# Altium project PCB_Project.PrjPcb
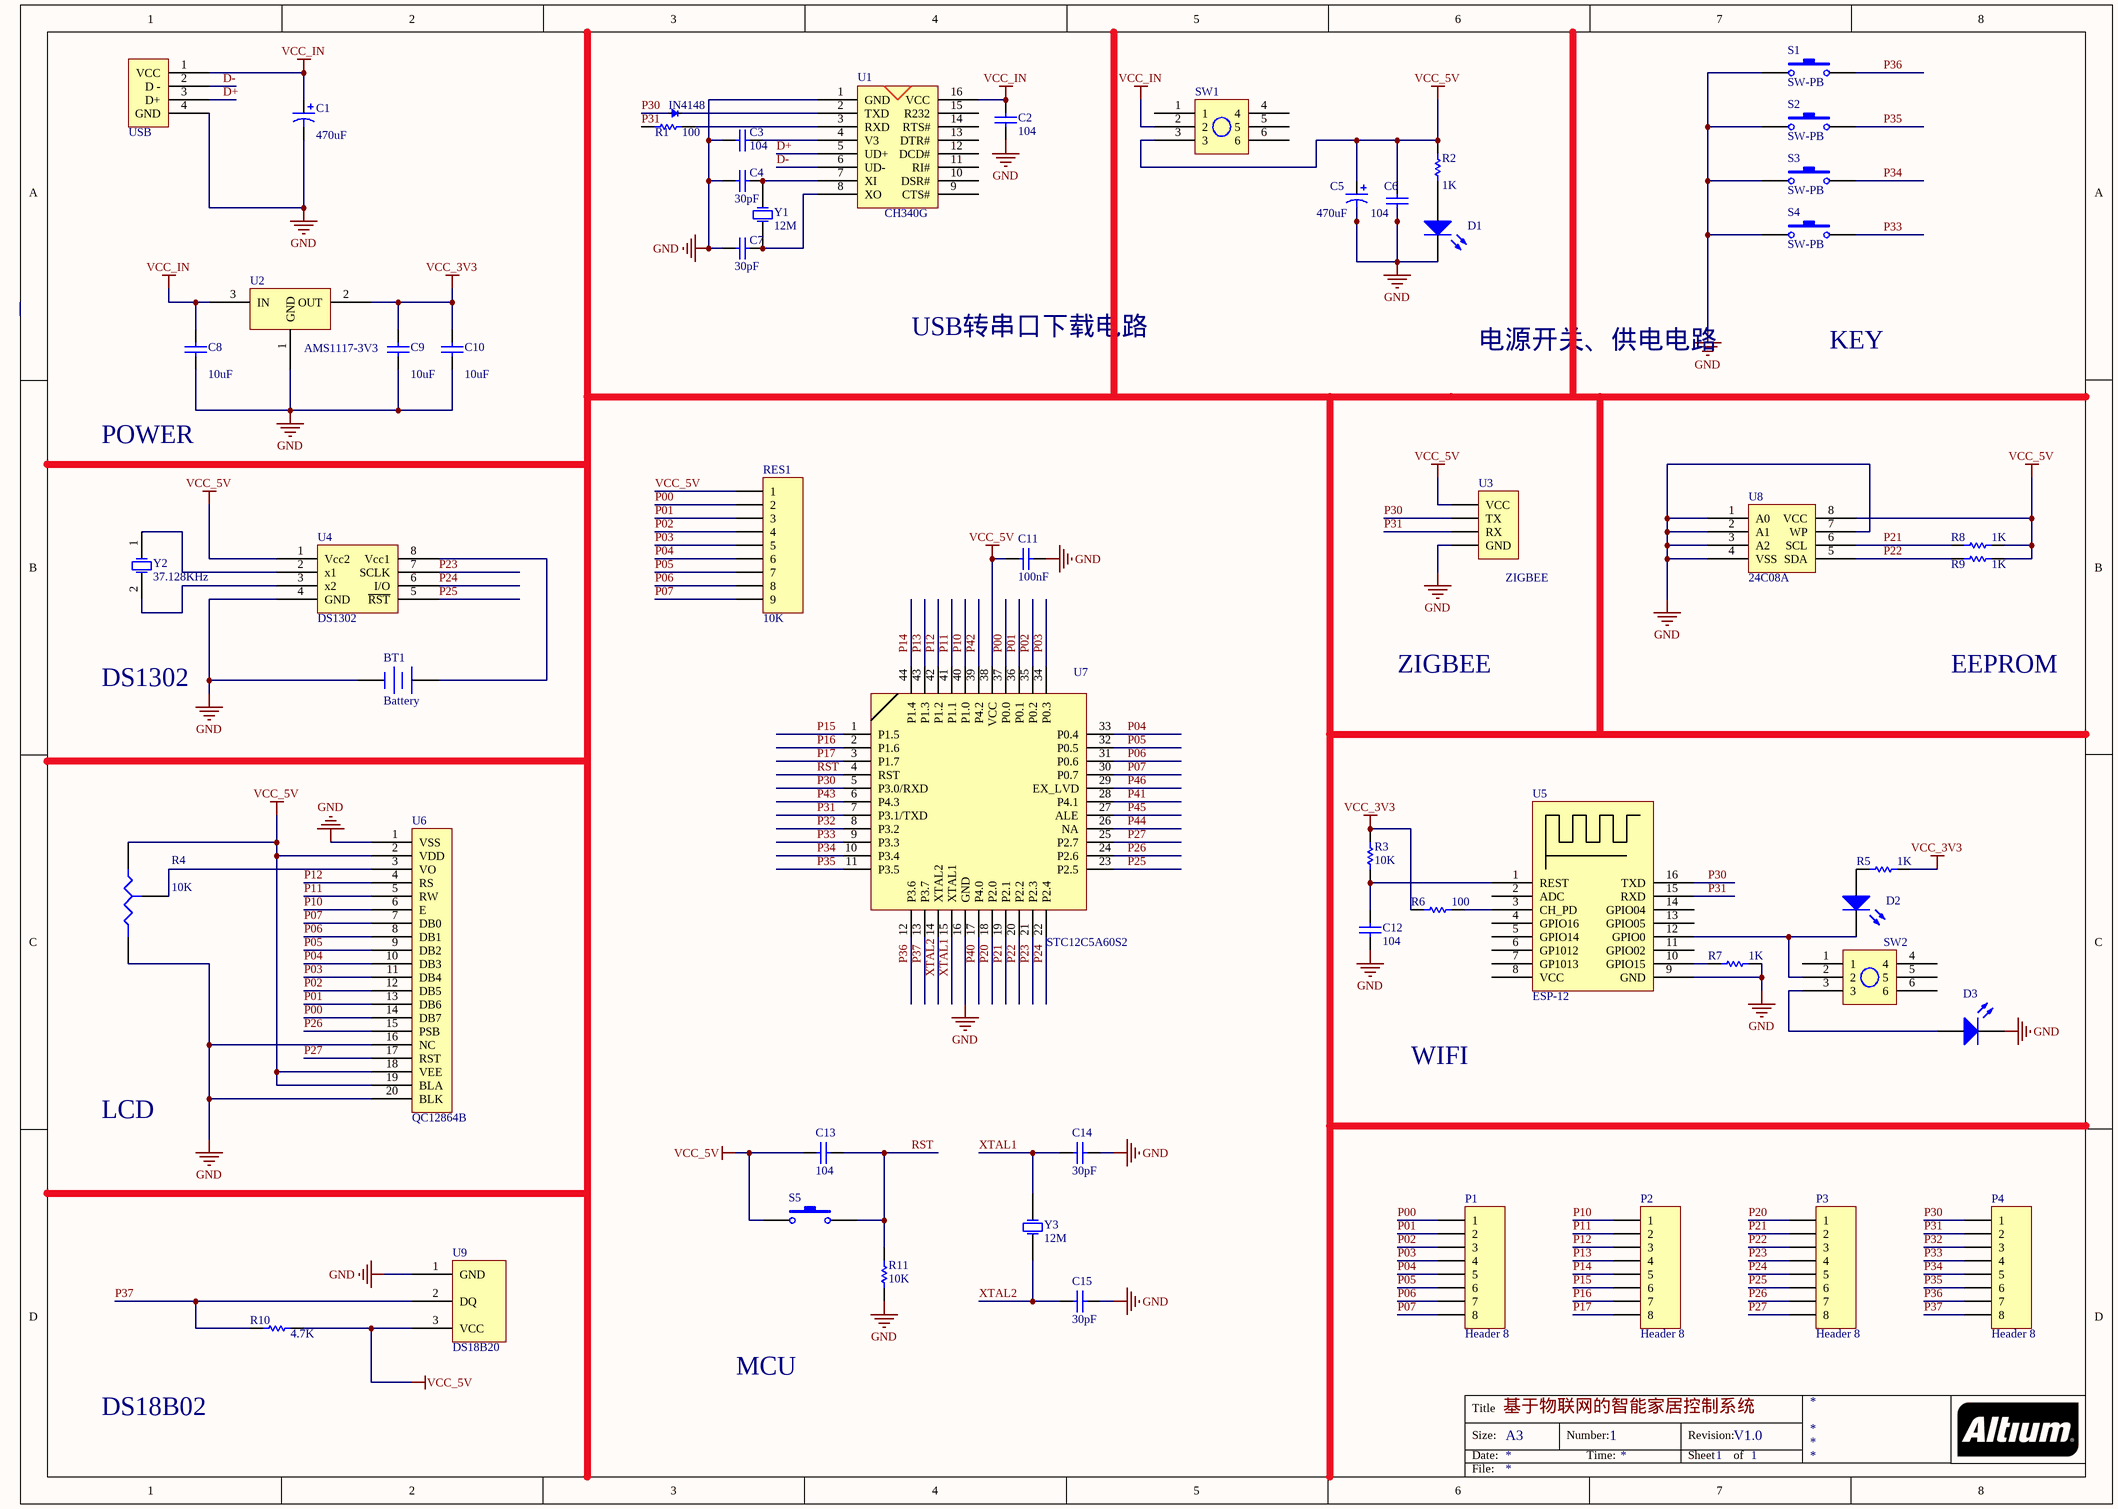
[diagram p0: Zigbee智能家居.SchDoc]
1 sheet, 56 parts. Net scope: global (net labels, ports and power ports of the same name join across sheets).
Board file: zigbee智能家居.PcbDoc

## Sheet Zigbee智能家居.SchDoc: 基于物联网的智能家居控制系统
size A3; DocumentNumber: 1; Revision: V1.0; SheetNumber: 1; SheetTotal: 1

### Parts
*1  USB  [USB-4-A-SMT]
BT1  Battery  [BATTERY]
C1  value 470uF  [8mm Cap+]  (hidden comment: Cap Pol1)
C2  value 104  [RAD-0.1]  (hidden comment: Cap)
C3  value 104  [RAD-0.1]  (hidden comment: Cap)
C4  value 30pF  [RAD-0.1]  (hidden comment: Cap)
C5  value 470uF  [8mm Cap+]  (hidden comment: Cap Pol1)
C6  value 104  [RAD-0.1]  (hidden comment: Cap)
C7  value 30pF  [RAD-0.1]  (hidden comment: Cap)
C8  value 10uF  [RAD-0.1]  (hidden comment: Cap)
C9  value 10uF  [RAD-0.1]  (hidden comment: Cap)
C10  value 10uF  [RAD-0.1]  (hidden comment: Cap)
C11  value 100nF  [RAD-0.1]  (hidden comment: Cap)
C12  value 104  [RAD-0.1]  (hidden comment: Cap)
C13  value 104  [RAD-0.1]  (hidden comment: Cap)
C14  value 30pF  [RAD-0.1]  (hidden comment: Cap)
C15  value 30pF  [RAD-0.1]  (hidden comment: Cap)
D1  LED3  [LED]  (value not drawn)
D2  LED3  [LED]  (value not drawn)
D3  LED3  [LED]  (value not drawn)
IN4148  IN4148  [LL-34]  (value not drawn)
P1  Header 8  [HDR1X8]
P2  Header 8  [HDR1X8]
P3  Header 8  [HDR1X8]
P4  Header 8  [HDR1X8]
R1  value 100  [AXIAL-0.3]  (hidden comment: Res1)
R2  value 1K  [AXIAL-0.3]  (hidden comment: Res1)
R3  value 10K  [AXIAL-0.3]  (hidden comment: Res1)
R4  value 10K  [变位器]  (hidden comment: Res Tap)
R5  value 1K  [AXIAL-0.3]  (hidden comment: Res1)
R6  value 100  [AXIAL-0.3]  (hidden comment: Res1)
R7  value 1K  [AXIAL-0.3]  (hidden comment: Res1)
R8  value 1K  [AXIAL-0.3]  (hidden comment: Res1)
R9  value 1K  [AXIAL-0.3]  (hidden comment: Res1)
R10  value 4.7K  [AXIAL-0.3]  (hidden comment: Res1)
R11  value 10K  [AXIAL-0.3]  (hidden comment: Res1)
RES1  10K  [HDR1X9]
S1  SW-PB  [6x6四脚开关]
S2  SW-PB  [6x6四脚开关]
S3  SW-PB  [6x6四脚开关]
S4  SW-PB  [6x6四脚开关]
S5  SW-PB  [6x6四脚开关]  (value not drawn)
SW1  Component_1  [6x6六脚开关]  (value not drawn)
SW2  Component_1  [6x6六脚开关]  (value not drawn)
U1  CH340G  [SOIC127P600X170-16N]
U2  AMS1117-3V3  [SOT223]
U3  ZIGBEE  [zigbee直插]
U4  DS1302  [DIP-8]
U5  ESP-12  [ESP-12]
U6  QC12864B  [SIP20]
U7  STC12C5A60S2  [LQFP44]
U8  24C08A  [dip-8]
U9  DS18B20  [TO92]
Y1  12M  [5mm晶振]
Y2  37.128KHz  [R38]
Y3  12M  [5mm晶振]

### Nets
GND: *1.4(GND) BT1.2(-) C1.2 C2.1 C3.1 C4.1 C5.2 C6.1 C7.1 C8.2 C9.2 C10.2 C11.2 C12.2 C14.1 C15.1 D1.2(K) D3.2(K) R4.2(B) R7.2 R11.1 S1.1 S2.1 S3.1 S4.1 U1.1(GND) U2.1(GND) U3.4(GND) U4.4(GND) U5.9(GND) U6.1(VSS) U6.16(NC) U6.20(BLK) U7.16(GND) U8.1(A0) U8.2(A1) U8.3(A2) U8.4(VSS) U8.7(WP) U9.1(GND)
VCC_3V3: C9.1 C10.1 R3.2 R5.2 R6.1 U2.2(OUT)
VCC_5V: C5.1 C6.2 C11.1 C13.2 R2.1 R4.1(A) R8.2 R9.2 R10.2 RES1.1 S5.1 SW1.3 U3.1(VCC) U4.1(Vcc2) U6.2(VDD) U6.18(VEE) U6.19(BLA) U7.38(VCC) U8.8(VCC) U9.3(VCC)
VCC_IN: *1.1(VCC) C1.1 C2.2 C8.1 SW1.2 U1.16(VCC) U2.3(IN)
D+: *1.3(D+) U1.5(UD+)
D-: *1.2(D_-) U1.6(UD-)
P00: P1.1 RES1.2 U6.14(DB7) U7.37(P0.0)
P01: P1.2 RES1.3 U6.13(DB6) U7.36(P0.1)
P02: P1.3 RES1.4 U6.12(DB5) U7.35(P0.2)
P03: P1.4 RES1.5 U6.11(DB4) U7.34(P0.3)
P04: P1.5 RES1.6 U6.10(DB3) U7.33(P0.4)
P05: P1.6 RES1.7 U6.9(DB2) U7.32(P0.5)
P06: P1.7 RES1.8 U6.8(DB1) U7.31(P0.6)
P07: P1.8 RES1.9 U6.7(DB0) U7.30(P0.7)
P10: P2.1 U6.6(E) U7.40(P1.0)
P11: P2.2 U6.5(RW) U7.41(P1.1)
P12: P2.3 U6.4(RS) U7.42(P1.2)
P13: P2.4 U7.43(P1.3)
P14: P2.5 U7.44(P1.4)
P15: P2.6 U7.1(P1.5)
P16: P2.7 U7.2(P1.6)
P17: P2.8 U7.3(P1.7)
P20: P3.1 U7.18(P2.0)
P21: P3.2 R8.1 U7.19(P2.1) U8.6(SCL)
P22: P3.3 R9.1 U7.20(P2.2) U8.5(SDA)
P23: P3.4 U4.7(SCLK) U7.21(P2.3)
P24: P3.5 U4.6(I/O) U7.22(P2.4)
P25: P3.6 U4.5(~{RST}) U7.23(P2.5)
P26: P3.7 U6.15(PSB) U7.24(P2.6)
P27: P3.8 U6.17(RST) U7.25(P2.7)
P30: IN4148.1 P4.1 U3.2(TX) U5.16(TXD) U7.5(P3.0/RXD)
P31: P4.2 R1.1 U3.3(RX) U5.15(RXD) U7.7(P3.1/TXD)
P32: P4.3 U7.8(P3.2)
P33: P4.4 S4.2 U7.9(P3.3)
P34: P4.5 S3.2 U7.10(P3.4)
P35: P4.6 S2.2 U7.11(P3.5)
P36: P4.7 S1.2 U7.12(P3.6)
P37: P4.8 R10.1 U7.13(P3.7) U9.2(DQ)
P40: U7.17(P4.0)
P41: U7.28(P4.1)
P42: U7.39(P4.2)
P43: U7.6(P4.3)
P44: U7.26(NA)
P45: U7.27(ALE)
P46: U7.29(EX_LVD)
RST: C13.1 R11.2 S5.2 U7.4(RST)
XTAL1: C14.2 U7.15(XTAL1) Y3.1(OSC1)
XTAL2: C15.2 U7.14(XTAL2) Y3.2(OSC2)
NetBT1_1: BT1.1(+) U4.8(Vcc1)
NetC3_2: C3.2 U1.4(V3)
NetC4_2: C4.2 U1.7(XI) Y1.2(OSC2)
NetC7_2: C7.2 U1.8(XO) Y1.1(OSC1)
NetC12_1: C12.1 R3.1 U5.1(REST)
NetD1_1: D1.1(A) R2.2
NetD2_1: D2.1(A) R5.1
NetD2_2: D2.2(K) SW2.2 U5.12(GPIO0)
NetD3_1: D3.1(A) SW2.3
NetIN4148_2: IN4148.2 U1.2(TXD)
NetR1_2: R1.2 U1.3(RXD)
NetR4_3: R4.3(TAP) U6.3(VO)
NetR6_2: R6.2 U5.3(CH_PD)
NetR7_1: R7.1 U5.10(GPIO15)
NetU4_2: U4.2(x1) Y2.1(OSC1)
NetU4_3: U4.3(x2) Y2.2(OSC2)

Not connected (* = marked no-connect by the designer): SW1 1 4 5 6; SW2 1 4 5 6; U1 9(CTS#) 10(DSR#) 11(RI#) 12(DCD#) 13(DTR#) 14(RTS#) 15(R232); U5 2(ADC) 4(GPIO16) 5(GPIO14) 6(GP1012) 7(GP1013) 8(VCC) 11(GPIO02) 13(GPIO05) 14(GPIO04)

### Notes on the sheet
- USB转串口下载电路
- 电源开关、供电电路
- KEY
- POWER
- DS1302
- ZIGBEE
- EEPROM
- LCD
- WIFI
- MCU
- DS18B02

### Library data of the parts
*1 = COMPONENT_1
BT1 = Battery: Multicell Battery
C1 C5 = Cap Pol1: Polarized Capacitor (Radial)
C2-C4 C6-C15 = Cap: Capacitor
D1-D3 = LED3: Typical BLUE SiC LED
IN4148 = 4148
P1-P4 = Header 8: Header, 8-Pin
R1-R3 R5-R11 = Res1: Resistor
R4 = Res Tap: Tapped Resistor; Sim Note: Enter the Resistance value and the set point into parameter fields.; Set Position: 0.5
RES1 = Header 9: Header, 9-Pin
S1-S5 = SW-PB: Switch
U1 U2 U5 = Component_1
U3 = Header 4: Header, 4-Pin
U6 = FM12864M
U8 = 24C64
Y1 Y3 = XTAL
Y2 = XTAL: Crystal Oscillator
